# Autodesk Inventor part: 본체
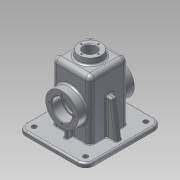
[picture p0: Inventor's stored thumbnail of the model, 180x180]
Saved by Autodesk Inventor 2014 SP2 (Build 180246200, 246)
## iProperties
Created: 2016-08
Part Number: 본체
Material: 알루미늄 6061
Document SubType Name: Modeling
Designer: user
Density: 2.71 g/cm^3
Appearance: 알루미늄 - 평지
Mass: 792.788 g
Surface Area: 919.428 cm^2
Volume: 292.542 cm^3
Author: user
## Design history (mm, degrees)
sketch "스케치1"
  geometry: L1 (-52.5, -60)-(52.5, -60); L2 (52.5, -60)-(52.5, 60); L3 (52.5, 60)-(-52.5, 60); L4 (-52.5, 60)-(-52.5, -60); L5 (-52.5, -60)-(52.5, 60); L6 (52.5, -60)-(-52.5, 60); 1 further point
  constraints: 12 end point, 2 midpoint, 2 parallel, 1 horizontal, 1 perpendicular
  dimensions: "d0" = 105 distance of L3.end L2.end; "d1" = 120 distance of L2.end L1.end
extrude "돌출1" new body sketch "스케치1" distance "d2" = 3; taper "d3" = 0 deg
sketch "스케치2"
  geometry: L1 (-57.5, -65)-(57.5, -65); L2 (57.5, -65)-(57.5, 65); L3 (57.5, 65)-(-57.5, 65); L4 (-57.5, 65)-(-57.5, -65); L5 (-57.5, -65)-(57.5, 65); L6 (57.5, -65)-(-57.5, 65); 1 further point
  constraints: 12 end point, 2 midpoint, 2 parallel, 1 horizontal, 1 perpendicular
  dimensions: "d4" = 115 distance of L3.end L2.end; "d5" = 130 distance of L2.end L1.end
extrude "돌출2" join sketch "스케치2" distance "d6" = 7; taper "d7" = 0 deg
sketch "스케치3"
  geometry: L1 (-32.5, -32.5)-(32.5, -32.5); L2 (32.5, -32.5)-(32.5, 32.5); L3 (32.5, 32.5)-(-32.5, 32.5); L4 (-32.5, 32.5)-(-32.5, -32.5); L5 (-32.5, -32.5)-(32.5, 32.5); L6 (32.5, -32.5)-(-32.5, 32.5); 1 further point
  constraints: 12 end point, 2 midpoint, 2 parallel, 1 horizontal, 1 perpendicular
  dimensions: "d8" = 65 distance of L3.end L2.end; "d9" = 65 distance of L2.end L1.end
extrude "돌출3" join sketch "스케치3" distance "d10" = 100; taper "d11" = 0 deg
sketch "스케치4"
  geometry: L1 (27.5, 27.5)-(-27.5, 27.5); L2 (-27.5, 27.5)-(-27.5, -27.5); L3 (-27.5, -27.5)-(27.5, -27.5); L4 (27.5, -27.5)-(27.5, 27.5); L5 (27.5, 27.5)-(-27.5, -27.5); L6 (-27.5, 27.5)-(27.5, -27.5); 3 further points
  constraints: 12 end point, 3 midpoint, 2 parallel, 1 coincident, 1 horizontal, 1 perpendicular
  dimensions: "d12" = 55 distance of L3.end L2.end; "d13" = 55 distance of L2.end L1.end
extrude "돌출4" cut sketch "스케치4" distance "d14" = 105; taper "d15" = 0 deg
sketch "스케치5"
  geometry: C1 r 27.5 at (32.5, 45); 1 further point
  constraints: 1 centre point, 1 vertical alignment
  dimensions: "d16" = 55 diameter of C1; "d17" = 55 distance of point (32.5, -10) C1.centre
extrude "돌출5" join sketch "스케치5" distance "d18" = 15; taper "d19" = 0 deg
sketch "스케치6"
  geometry: C1 r 27.5 at (32.5, -45); 1 further point
  constraints: 1 centre point, 1 vertical alignment
  dimensions: "d20" = 55 diameter of C1; "d21" = 55 distance of C1.centre point (32.5, 10)
extrude "돌출6" join sketch "스케치6" distance "d22" = 15; taper "d23" = 0 deg
sketch "스케치7"
  geometry: C1 r 17.5 at (0, 0); 1 further point
  constraints: 1 centre point, 1 vertical alignment
  dimensions: "d24" = 35 diameter of C1; "d25" = 55 distance of point (0, -55) C1.centre
extrude "돌출7" cut sketch "스케치7" distance "d26" = 17; taper "d27" = 0 deg
sketch "스케치8"
  geometry: L1 (27.5, 55)-(-27.5, 55) reference; C1 r 17.5 at (0, 0); 2 further points
  constraints: 1 centre point, 1 midpoint, 1 vertical alignment
  dimensions: "d28" = 35 diameter of C1; "d29" = 55 distance of C1.centre point (0, 55)
extrude "돌출8" cut sketch "스케치8" distance "d30" = 17; taper "d31" = 0 deg
sketch "스케치9"
  geometry: C1 r 15 at (0, 0); 1 further point
  constraints: 1 centre point, 1 vertical alignment
  dimensions: "d32" = 30 diameter of C1; "d33" = 55 distance of point (0, 55) C1.centre
extrude "돌출9" cut sketch "스케치9" stored distance "d34" = 17; taper "d35" = 0 deg
sketch "스케치10"
  geometry: C1 r 20 at (0, 0); 1 further point
  constraints: 1 centre point, 1 coincident
  dimensions: "d36" = 40 diameter of C1
extrude "돌출10" join sketch "스케치10" distance "d37" = 10; taper "d38" = -7 deg
sketch "스케치11"
  geometry: C1 r 10.5 at (0, 0); 1 further point
  constraints: 1 centre point, 1 coincident
  dimensions: "d39" = 21 diameter of C1
extrude "돌출11" cut sketch "스케치11" stored distance "d40" = 10; taper "d41" = 0 deg
fillet "모깎기1" dims "d42" = 8
fillet "모깎기2" dims "d43" = 8
sketch "스케치12" dims "d44" = 42
  geometry: 3 further points
  constraints: 3 vertical alignment, 2 other
  dimensions: "d45" = 55 distance of point (0, -55) point (0, 0)
hole "구멍1" sketch "스케치12" at (0, 21) diameter "d46" = 3.242; stored, may be unused: countersink angle "d50" = 90 deg, drill point angle "d52" = 118 deg; dims "d47" = 8, "d48" = 4, "d49" = 2, "d51" = 10
sketch "스케치13" dims "d56" = 42
  geometry: 3 further points
  constraints: 3 vertical alignment, 2 other
  dimensions: "d57" = 55 distance of point (0, 0) point (0, 55)
hole "구멍2" sketch "스케치13" at (0, -21) diameter "d58" = 3.242; stored, may be unused: countersink angle "d62" = 90 deg, drill point angle "d64" = 118 deg; dims "d59" = 8, "d60" = 4, "d61" = 2, "d63" = 10
sketch "스케치14"
  geometry: L1 (-57.5, -65)-(57.5, -65) reference; L2 (57.5, -65)-(57.5, 65) reference; C1 r 4 at (43.5, -51); 1 further point
  constraints: 1 centre point
  dimensions: "d68" = 8 diameter of C1; "d69" = 14 distance from line of L1 C1.centre; "d70" = 14 distance from line of C1.centre L2
extrude "돌출12" cut sketch "스케치14" stored distance "d71" = 10; taper "d72" = 0 deg
sketch "스케치15"
  geometry: L1 (27.5, 27.5)-(-27.5, 27.5) reference; L2 (3, 27.5)-(3, 42.5); L3 (3, 42.5)-(-3, 42.5); L4 (-3, 42.5)-(-3, 27.5); 2 further points
  constraints: 6 end point, 2 parallel, 2 point on line, 1 midpoint, 1 perpendicular, 1 vertical alignment
  dimensions: "d79" = 6 distance of L2.end L3.end; "d80" = 15 distance between parallel lines of L1 L3
extrude "돌출13" join sketch "스케치15" stored distance "d81" = 10; taper "d82" = 0 deg
sketch "스케치16"
  geometry: L1 (39.5, 10)-(47.5, 10) reference; L2 (49.5, 10)-(41.068, 70); L3 (57.5, 3)-(57.5, 10) reference; L4 (41.068, 70)-(32.5, 70); L5 (32.5, 102)-(32.5, 10) reference; L6 (52.5, 0)-(-52.5, 0) reference; 1 further point
  constraints: 4 end point, 2 point on line, 1 perpendicular
  dimensions: "d83" = 8 deg angle of L3 L2; "d84" = 8 distance from line of L3 L2.start; "d113" = 70 distance between parallel lines of L6 L4
feature "리브1" sketch "스케치16" dims "d86" = 1, "d87" = 10, "d88" = 0, "d89" = 0, "d90" = 1, "d91" = 1
fillet "모깎기3" dims "d92" = 0.3
fillet "모깎기4" dims "d93" = 0.3
fillet "모깎기5" dims "d94" = 9
fillet "모깎기6" dims "d95" = 14
fillet "모깎기7" dims "d96" = 3
fillet "모깎기8" dims "d97" = 3
fillet "모깎기9" dims "d98" = 3
fillet "모깎기10" dims "d99" = 3
fillet "모깎기11" dims "d100" = 3
fillet "모깎기12" dims "d101" = 1
fillet "모깎기13" dims "d102" = 3
fillet "모깎기14" dims "d103" = 3
fillet "모깎기15" dims "d104" = 3
fillet "모깎기16" dims "d105" = 3
fillet "모깎기17" dims "d106" = 3
chamfer "모따기1" distance "d107" = 1; stored, may be unused: second distance "d108" = 2, angle "d109" = 45 deg
chamfer "모따기2" distance "d110" = 1; stored, may be unused: second distance "d111" = 2, angle "d112" = 45 deg
sketch "스케치17" dims "d114" = 29
  geometry: 3 further points
  constraints: 2 vertical alignment, 1 coincident, 2 other
hole "구멍3" sketch "스케치17" at (0, 14.5) diameter "d115" = 2.459; stored, may be unused: countersink angle "d119" = 90 deg, drill point angle "d121" = 118 deg; dims "d116" = 7, "d117" = 4, "d118" = 2, "d120" = 9
chamfer "모따기3" distance "d125" = 1; stored, may be unused: second distance "d126" = 2, angle "d127" = 45 deg
node "작업 평면1"
sketch "스케치18"
  geometry: L1 (43.272, -18)-(5.728, -18) reference; L2 (57, 0)-(57, 91) reference; 2 further points
  constraints: 1 vertical alignment, 1 other
  dimensions: "d130" = 32.5 distance from line of L2 point (24.5, 8) (derived); "d133" = 26 distance from line of L1 point (24.5, 8)
feature "엠보싱1" sketch "스케치18" dims "d8" = 65, "d9" = 65, "d131" = 0.5, "d132" = 0
node "솔리드1"
pattern_circular "원형 패턴1" dims angle "d54" = 360 deg
pattern_circular "원형 패턴2" dims angle "d66" = 360 deg
pattern_linear "직사각형 패턴1" dims "d75" = 87, "d78" = 102
mirror "대칭1"
mirror "대칭2"
pattern_circular "원형 패턴3" dims angle "d123" = 360 deg
other parameters: "d128" = 37.5
